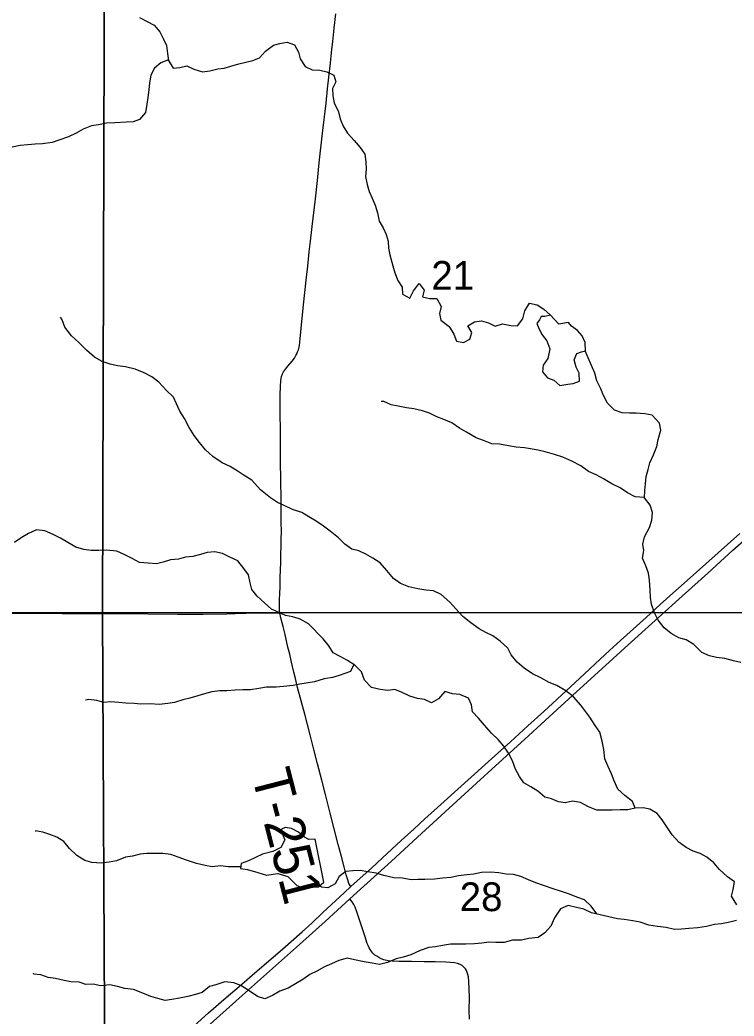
# Model space of a CAD drawing. Extents: x 0 to 34, y 0 to 22.
# Drawn here: x 4.949 to 5.987, y 18.295 to 19.744 of the extents above; entities that cross this region are included whole.
import ezdxf

# ---------------------------------------------------------------- set-up
doc = ezdxf.new("R2010")
doc.units = 0
for name, color, linetype in [('GM_X_Minor_Lake', 7, 'Continuous'), ('GM_X_Minor_River', 7, 'Continuous'), ('GM_X_Section', 7, 'Continuous'), ('GM_X_Section_Text', 7, 'Continuous'), ('GM_X_Township_Road', 7, 'Continuous'), ('GM_X_Township_Road_Text', 7, 'Continuous'), ('GM_X_US_Route', 7, 'Continuous')]:
    doc.layers.add(name, color=color, linetype=linetype)

msp = doc.modelspace()

# ---------------------------------------------------------------- linework, layer by layer
at = {"layer": 'GM_X_Minor_Lake'}
for points in [[(5.7201, 19.3148), (5.7118, 19.3127), (5.7065, 19.3127), (5.7038, 19.3082), (5.7003, 19.3025), (5.7033, 19.2945), (5.7078, 19.2861), (5.7145, 19.2773), (5.719, 19.2659), (5.7162, 19.2519), (5.7093, 19.2421), (5.7085, 19.2323), (5.7156, 19.2238), (5.725, 19.2203), (5.7337, 19.2123), (5.745, 19.2144), (5.753, 19.2155), (5.7621, 19.2188), (5.7618, 19.2306), (5.7574, 19.239), (5.7544, 19.2496), (5.7583, 19.2591), (5.7651, 19.2613), (5.7708, 19.2628), (5.7705, 19.2749), (5.7661, 19.2848), (5.759, 19.2925), (5.7503, 19.299), (5.7462, 19.304), (5.7321, 19.3018)], [(5.7321, 19.3018), (5.7201, 19.3148)], [(5.3778, 18.5526), (5.3687, 18.5523), (5.3623, 18.5558), (5.3536, 18.563), (5.3434, 18.5685), (5.334, 18.5697), (5.3287, 18.5671), (5.3301, 18.561), (5.3338, 18.5519), (5.3277, 18.5405), (5.3163, 18.5349), (5.3011, 18.5309), (5.2809, 18.5213), (5.2703, 18.5176), (5.2695, 18.51), (5.2793, 18.5088), (5.2944, 18.5041), (5.3069, 18.5005), (5.3236, 18.503), (5.3383, 18.4983), (5.3511, 18.4853), (5.3624, 18.481), (5.3745, 18.4828), (5.3825, 18.4835), (5.3905, 18.4902)], [(5.3905, 18.4902), (5.3778, 18.5526)]]:
    msp.add_lwpolyline(points, dxfattribs=at)
at = {"layer": 'GM_X_Minor_River'}
for points in [[(5.1225, 19.7475), (5.1338, 19.7417), (5.1436, 19.7363), (5.1522, 19.7267), (5.1575, 19.7164), (5.1615, 19.7069), (5.163, 19.6955), (5.1648, 19.6852), (5.1715, 19.6738), (5.181, 19.6748), (5.1912, 19.6774), (5.2014, 19.6727), (5.2142, 19.6688), (5.2248, 19.6702), (5.2362, 19.6728), (5.2457, 19.6742), (5.2552, 19.6771), (5.267, 19.6801), (5.2772, 19.6826), (5.2871, 19.6852), (5.2969, 19.6889), (5.3057, 19.6986), (5.3172, 19.7073), (5.3267, 19.7098), (5.3373, 19.7116), (5.3479, 19.7081), (5.3538, 19.6974), (5.356, 19.6875), (5.3631, 19.6765), (5.3737, 19.6718), (5.3846, 19.6709), (5.3948, 19.6689), (5.405, 19.6639), (5.408, 19.654), (5.403, 19.6442), (5.4036, 19.6336), (5.4054, 19.6237), (5.4118, 19.6107), (5.4143, 19.6001), (5.4184, 19.5898), (5.4248, 19.5795), (5.4345, 19.5688), (5.4431, 19.5585), (5.4499, 19.5489), (5.4513, 19.5379), (5.452, 19.5269), (5.4511, 19.5163), (5.4533, 19.5049), (5.4562, 19.4946), (5.4607, 19.4851), (5.4651, 19.4748), (5.4685, 19.4637), (5.471, 19.4516), (5.4766, 19.4417), (5.4811, 19.4321), (5.484, 19.4222), (5.4843, 19.4124), (5.4865, 19.4025), (5.4909, 19.3865), (5.4935, 19.3762), (5.4979, 19.3652), (5.5043, 19.3553), (5.5049, 19.3454), (5.5155, 19.3396), (5.5209, 19.3502), (5.5289, 19.3607), (5.5364, 19.3512), (5.5341, 19.3413), (5.5439, 19.3389), (5.5545, 19.3388), (5.5612, 19.3274), (5.5588, 19.3172), (5.5607, 19.3073), (5.5727, 19.2985), (5.5794, 19.287), (5.5831, 19.2771), (5.5933, 19.2751), (5.6028, 19.2799), (5.6056, 19.2898), (5.5996, 19.2993), (5.6095, 19.3053)], [(5.1646, 19.6863), (5.1537, 19.6819), (5.1442, 19.674), (5.1388, 19.6638), (5.1372, 19.6525), (5.136, 19.6423), (5.1348, 19.6313), (5.1332, 19.6214), (5.1312, 19.6097), (5.1227, 19.5995), (5.1133, 19.5958), (5.1034, 19.5955), (5.0864, 19.5946), (5.0746, 19.5939), (5.0629, 19.5917), (5.0526, 19.5899), (5.0405, 19.5851), (5.0306, 19.5795), (5.0192, 19.574), (5.0051, 19.5692), (4.9956, 19.5658), (4.9816, 19.5641), (4.9706, 19.5634), (4.96, 19.5624), (4.949, 19.5614), (4.9372, 19.5592)], [(5.6095, 19.3053), (5.6197, 19.3067), (5.6299, 19.3036), (5.6397, 19.2986), (5.65, 19.3023), (5.6621, 19.2999), (5.6719, 19.2994), (5.6796, 19.3096), (5.6827, 19.3213), (5.6896, 19.3322), (5.7006, 19.3298), (5.7104, 19.3233), (5.7198, 19.3148)], [(5.8428, 18.5977), (5.8391, 18.6076), (5.8282, 18.6161), (5.818, 18.6253), (5.8124, 18.6375), (5.8087, 18.6478), (5.8032, 18.6592), (5.7987, 18.6695), (5.7973, 18.6832), (5.7951, 18.6953), (5.7918, 18.7083), (5.7851, 18.7182), (5.7769, 18.73), (5.7638, 18.7476), (5.7533, 18.7599), (5.7424, 18.7687), (5.7292, 18.7764), (5.7179, 18.7807), (5.7058, 18.7873), (5.6937, 18.7934), (5.6817, 18.8015), (5.6715, 18.8104), (5.6629, 18.8207), (5.6577, 18.8306), (5.6468, 18.8409), (5.6363, 18.8486), (5.6261, 18.8533), (5.6163, 18.8587), (5.6039, 18.8672), (5.5926, 18.8764), (5.5821, 18.8879), (5.5738, 18.8974), (5.561, 18.9086), (5.5497, 18.914), (5.5388, 18.9148), (5.527, 18.9169), (5.5142, 18.9196), (5.5021, 18.9247), (5.4919, 18.932), (5.4818, 18.9435), (5.4721, 18.9546), (5.4615, 18.9615), (5.4513, 18.9673), (5.4415, 18.9723), (5.431, 18.9743), (5.4208, 18.9816), (5.4118, 18.9912), (5.3998, 19.0008), (5.39, 19.0081), (5.3794, 19.0154), (5.3685, 19.0216), (5.3583, 19.0278), (5.3451, 19.0324), (5.333, 19.0382), (5.3232, 19.0425), (5.3131, 19.0491), (5.2984, 19.061), (5.286, 19.0747), (5.2747, 19.0817), (5.2646, 19.0882), (5.2544, 19.0948), (5.2427, 19.1002), (5.2291, 19.1091), (5.2186, 19.119), (5.2096, 19.1294), (5.2018, 19.1397), (5.1947, 19.1515), (5.188, 19.1645), (5.1809, 19.1752), (5.1764, 19.1858), (5.1719, 19.1954), (5.1614, 19.2057), (5.1505, 19.2172), (5.1404, 19.2253), (5.1295, 19.2311), (5.1162, 19.2365), (5.1023, 19.2397), (5.0905, 19.2413), (5.08, 19.2437), (5.0682, 19.2472), (5.0569, 19.2538), (5.0453, 19.2641), (5.0344, 19.2749), (5.0235, 19.2848), (5.0141, 19.2974), (5.0101, 19.3081), (5.0078, 19.3119)], [(5.9511, 18.8194), (5.9401, 18.8241), (5.9281, 18.8359), (5.9172, 18.8425), (5.9066, 18.8456), (5.8953, 18.8518), (5.8852, 18.8603), (5.8765, 18.8713), (5.8709, 18.882), (5.8669, 18.8946), (5.8655, 18.9041), (5.8648, 18.9147), (5.8638, 18.9295), (5.8623, 18.9394), (5.8583, 18.9504), (5.8538, 18.9615), (5.8554, 18.9725), (5.8544, 18.982), (5.8567, 18.9926), (5.864, 19.0058), (5.8672, 19.0167), (5.8684, 19.0277), (5.8647, 19.0384), (5.8565, 19.0491), (5.8569, 19.0597), (5.8578, 19.0696), (5.859, 19.0802), (5.8621, 19.0904), (5.8645, 19.1002), (5.8699, 19.1119), (5.8745, 19.1237), (5.8765, 19.1339), (5.8804, 19.1475), (5.8782, 19.1578), (5.8677, 19.1696), (5.8571, 19.1712), (5.8446, 19.1725), (5.8348, 19.1722), (5.8242, 19.1727), (5.8129, 19.1766), (5.8027, 19.1866), (5.7968, 19.198), (5.7931, 19.2075), (5.7871, 19.2194), (5.7842, 19.2304), (5.7793, 19.2418), (5.7749, 19.2529), (5.7704, 19.2627)], [(5.8565, 19.0498), (5.8428, 19.0504), (5.8319, 19.0562), (5.8214, 19.0638), (5.8089, 19.0693), (5.7969, 19.077), (5.7863, 19.0824), (5.775, 19.0874), (5.7641, 19.0955), (5.7509, 19.1025), (5.7381, 19.1083), (5.7256, 19.1122), (5.7124, 19.1161), (5.7018, 19.1185), (5.6821, 19.1217), (5.67, 19.123), (5.6591, 19.1246), (5.6458, 19.127), (5.6345, 19.1279), (5.6224, 19.1326), (5.6118, 19.1365), (5.5979, 19.1446), (5.5877, 19.1507), (5.5764, 19.158), (5.5651, 19.1631), (5.5549, 19.167), (5.544, 19.1724), (5.5338, 19.1755), (5.5213, 19.1787), (5.5107, 19.1799), (5.4986, 19.1823), (5.4884, 19.1843), (5.4775, 19.189), (5.4737, 19.1894)], [(5.2208, 18.9695), (5.2113, 18.9666), (5.1999, 18.964), (5.1893, 18.963), (5.1794, 18.9601), (5.1676, 18.959), (5.157, 18.9554), (5.1472, 18.9532), (5.135, 18.9541), (5.1226, 18.9553), (5.112, 18.9607), (5.1003, 18.9665), (5.0897, 18.9716), (5.0746, 18.9732), (5.0636, 18.9726), (5.0523, 18.9727), (5.0417, 18.9739), (5.03, 18.9775), (5.0183, 18.984), (5.0077, 18.9906), (4.9968, 18.996), (4.9851, 19.001), (4.9726, 19.0027), (4.9612, 18.9971), (4.9506, 18.9908), (4.941, 18.984)], [(5.9908, 18.4574), (5.9829, 18.4697), (5.9857, 18.4795), (5.9873, 18.4909), (5.9771, 18.4978), (5.9655, 18.5085), (5.9572, 18.5185), (5.9474, 18.5265), (5.9373, 18.5319), (5.9271, 18.5355), (5.9173, 18.5405), (5.9063, 18.5482), (5.8966, 18.5589), (5.8824, 18.5807), (5.8749, 18.5902), (5.8643, 18.5964), (5.8545, 18.5984), (5.8428, 18.5977), (5.8322, 18.5956), (5.8212, 18.5953), (5.8094, 18.5947), (5.7871, 18.5949), (5.775, 18.5999), (5.7637, 18.6061), (5.752, 18.6081), (5.7414, 18.6056), (5.7315, 18.6072), (5.7213, 18.6114), (5.7115, 18.6138), (5.7017, 18.6226), (5.6912, 18.6288), (5.681, 18.6346), (5.675, 18.6441), (5.6691, 18.6544), (5.6646, 18.6666), (5.659, 18.6777), (5.6519, 18.688), (5.6441, 18.6979), (5.6343, 18.7068), (5.6242, 18.7186), (5.6152, 18.7286), (5.6065, 18.7381), (5.6051, 18.748), (5.6007, 18.7579), (5.5882, 18.763), (5.5776, 18.7642), (5.5663, 18.7677), (5.5571, 18.7568), (5.5468, 18.7512), (5.5366, 18.7559), (5.5264, 18.7571), (5.5155, 18.7607), (5.5045, 18.7661), (5.4936, 18.7704), (5.4834, 18.7689), (5.4724, 18.7706), (5.4599, 18.7733), (5.4494, 18.7841), (5.445, 18.7962), (5.4356, 18.8058), (5.425, 18.8128), (5.4141, 18.8185), (5.4039, 18.8236), (5.3976, 18.8339), (5.3893, 18.8442), (5.3683, 18.8657), (5.3562, 18.8726), (5.3453, 18.8761), (5.3347, 18.8781), (5.3241, 18.8828), (5.3143, 18.8874), (5.3042, 18.8963), (5.2933, 18.9062), (5.2858, 18.9158), (5.2832, 18.9257), (5.2811, 18.9371), (5.2743, 18.9466), (5.2653, 18.9577), (5.254, 18.9631), (5.2431, 18.9682), (5.2321, 18.9706), (5.2208, 18.9695)], [(5.9964, 18.8099), (5.9858, 18.8122), (5.9734, 18.8154), (5.9613, 18.817), (5.9511, 18.8194)], [(5.4342, 18.8067), (5.4294, 18.7964), (5.4127, 18.7909), (5.4032, 18.7879), (5.3907, 18.7858), (5.3767, 18.7817), (5.3649, 18.7796), (5.3554, 18.7781), (5.346, 18.776), (5.3319, 18.775), (5.3213, 18.7739), (5.3073, 18.7737), (5.2959, 18.7719), (5.2838, 18.7701), (5.2728, 18.7698), (5.2615, 18.7696), (5.2493, 18.7686), (5.2395, 18.7683), (5.2277, 18.7669), (5.2171, 18.7643), (5.2072, 18.7614), (5.1958, 18.7577), (5.1856, 18.7555), (5.1735, 18.7515), (5.1636, 18.75), (5.1511, 18.7486), (5.1378, 18.7495), (5.1246, 18.7493), (5.1147, 18.7501), (5.1026, 18.7506), (5.0924, 18.7515), (5.0807, 18.7524), (5.0705, 18.7517), (5.0603, 18.7545), (5.0489, 18.7557), (5.044, 18.755)], [(5.2698, 18.5126), (5.2513, 18.5124), (5.24, 18.5141), (5.2282, 18.5127), (5.218, 18.5147), (5.2055, 18.5174), (5.1908, 18.5221), (5.1787, 18.5264), (5.1678, 18.5303), (5.1564, 18.532), (5.1451, 18.5317), (5.133, 18.5318), (5.1235, 18.5308), (5.1121, 18.5282), (5.1022, 18.5268), (5.0889, 18.5212), (5.0783, 18.5194), (5.0669, 18.5177), (5.0533, 18.5189), (5.0431, 18.5217), (5.0315, 18.529), (5.0209, 18.539), (5.0123, 18.5493), (5.0021, 18.5555), (4.9923, 18.5594), (4.9818, 18.5629), (4.9712, 18.5649), (4.9715, 18.5641)], [(5.7871, 18.4441), (5.7791, 18.4553), (5.7693, 18.4645), (5.758, 18.4684), (5.7478, 18.4727), (5.7357, 18.4766), (5.724, 18.4805), (5.71, 18.4852), (5.6987, 18.4895), (5.6878, 18.4934), (5.6768, 18.4984), (5.6663, 18.5012), (5.6553, 18.5017), (5.6447, 18.5037), (5.6326, 18.5049), (5.6197, 18.5043), (5.6087, 18.5021), (5.5985, 18.5011), (5.5863, 18.4993), (5.5753, 18.4971), (5.5628, 18.4961), (5.5511, 18.4947), (5.5374, 18.4941), (5.5272, 18.4942), (5.5174, 18.4935), (5.5049, 18.4959), (5.492, 18.4964), (5.4777, 18.5), (5.4667, 18.5031), (5.4546, 18.5051), (5.4433, 18.5072), (5.4327, 18.5069), (5.4224, 18.5055), (5.4129, 18.4987), (5.4067, 18.4878), (5.3961, 18.4818), (5.3872, 18.4828), (5.3843, 18.485)], [(5.9902, 18.4343), (5.9807, 18.4321), (5.9686, 18.4296), (5.9583, 18.4285), (5.9466, 18.4256), (5.9341, 18.4238), (5.9208, 18.4228), (5.9106, 18.4218), (5.9003, 18.4215), (5.8879, 18.4243), (5.8754, 18.4256), (5.8629, 18.4276), (5.8501, 18.4319), (5.8395, 18.4339), (5.827, 18.4359), (5.8172, 18.4371), (5.7794, 18.4458), (5.7684, 18.4509), (5.7579, 18.4536), (5.7458, 18.4564), (5.7347, 18.4516), (5.7259, 18.4384), (5.7205, 18.4263), (5.7117, 18.4165), (5.7022, 18.4098), (5.6878, 18.4084), (5.6779, 18.4058), (5.6647, 18.406), (5.6525, 18.4023), (5.6404, 18.4024), (5.6302, 18.4029), (5.6203, 18.4015), (5.6097, 18.4004), (5.5969, 18.4002), (5.5866, 18.4003), (5.5745, 18.4), (5.5628, 18.3982), (5.5529, 18.3961), (5.543, 18.395), (5.5305, 18.391), (5.5168, 18.3847), (5.5058, 18.381), (5.4956, 18.3788), (5.483, 18.3736), (5.4713, 18.3707), (5.4607, 18.3723), (5.4493, 18.3743), (5.435, 18.3771), (5.4244, 18.3795), (5.4122, 18.3762), (5.4016, 18.3717), (5.3913, 18.3669), (5.3803, 18.3609), (5.37, 18.3561), (5.3601, 18.3486), (5.3491, 18.3423), (5.3388, 18.3359), (5.3267, 18.3315), (5.316, 18.3255), (5.3046, 18.3207), (5.294, 18.3238), (5.2805, 18.3331), (5.2699, 18.34), (5.2597, 18.3439), (5.2465, 18.3452), (5.2336, 18.3407), (5.2241, 18.3386), (5.2138, 18.3299), (5.2039, 18.327), (5.1929, 18.3241), (5.1804, 18.3215), (5.1694, 18.3197), (5.1599, 18.3183), (5.149, 18.3211), (5.1391, 18.3238), (5.1271, 18.3289), (5.1139, 18.3343), (5.1014, 18.3356), (5.0904, 18.3383), (5.0795, 18.3407), (5.0662, 18.3393), (5.0552, 18.3417), (5.0446, 18.3414), (5.0348, 18.345), (5.0227, 18.3451), (5.0129, 18.3471), (5.0004, 18.3502), (4.9898, 18.3518), (4.9789, 18.3557), (4.969, 18.3566), (4.9683, 18.3581)]]:
    msp.add_lwpolyline(points, dxfattribs=at)
at = {"layer": 'GM_X_Section'}
for points in [[(6.0796, 19.8902), (6.0998, 18.8817), (5.0689, 18.882), (5.0715, 19.8844)], [(5.0715, 19.8844), (5.0689, 18.882), (4.08, 18.8834), (4.0799, 19.8852)], [(5.0723, 18.2003), (5.0689, 18.882), (4.08, 18.8834), (4.0919, 18.2003)], [(5.9868, 17.8455), (6.1027, 17.8448), (6.0998, 18.8817), (5.0689, 18.882), (5.0723, 18.2003), (5.9868, 18.2003)]]:
    msp.add_lwpolyline(points, close=True, dxfattribs=at)
at = {"layer": 'GM_X_Township_Road'}
for points in [[(5.3266, 18.8816), (5.3261, 18.8858), (5.326, 18.8913), (5.326, 18.8959), (5.3261, 18.8999), (5.3262, 18.9033), (5.3264, 18.9079), (5.3268, 18.9211), (5.327, 18.9273), (5.3271, 18.9304), (5.3272, 18.9334), (5.3279, 18.9552), (5.3281, 18.9681), (5.3283, 18.9785), (5.3285, 18.9906), (5.3288, 18.9986), (5.3285, 19.0152), (5.3286, 19.0331), (5.3284, 19.0514), (5.3281, 19.0702), (5.3276, 19.1069), (5.3276, 19.1264), (5.3275, 19.1491), (5.3272, 19.1705), (5.3271, 19.1984), (5.3274, 19.2117), (5.328, 19.2194), (5.3291, 19.2257), (5.3304, 19.2297), (5.332, 19.2324), (5.3347, 19.2361), (5.3379, 19.2404), (5.3446, 19.2481), (5.3477, 19.2524), (5.3496, 19.256), (5.3513, 19.2588), (5.3524, 19.2617), (5.3534, 19.2644), (5.3549, 19.2705), (5.356, 19.2802), (5.3577, 19.2956), (5.3611, 19.3298), (5.3653, 19.3702), (5.367, 19.386), (5.3692, 19.4068), (5.3711, 19.4226), (5.3737, 19.4439), (5.3781, 19.4842), (5.3811, 19.5108), (5.3838, 19.5363), (5.3885, 19.5794), (5.3936, 19.623), (5.3959, 19.6438), (5.3978, 19.6609), (5.4002, 19.6813), (5.4017, 19.6967), (5.4033, 19.7129), (5.4055, 19.7324), (5.408, 19.7531)], [(4.8734, 18.8813), (4.9511, 18.8812), (5.0101, 18.8808), (5.0381, 18.881), (5.0536, 18.8811), (5.0909, 18.8807), (5.1779, 18.8802), (5.2152, 18.8798), (5.2494, 18.8804), (5.2618, 18.8808), (5.2773, 18.8813), (5.2989, 18.8817), (5.3114, 18.8817), (5.3207, 18.8817), (5.3266, 18.8816)], [(5.4298, 18.4837), (5.427, 18.4885), (5.4251, 18.4936), (5.4229, 18.5009), (5.4199, 18.5126), (5.4161, 18.5275), (5.4115, 18.5452), (5.4049, 18.5699), (5.3998, 18.5906), (5.3929, 18.6178), (5.3876, 18.6388), (5.3812, 18.6624), (5.3748, 18.687), (5.3704, 18.7044), (5.3628, 18.7345), (5.3524, 18.7735), (5.3492, 18.7865), (5.3468, 18.7955), (5.3435, 18.81), (5.3408, 18.8218), (5.3383, 18.8322), (5.3362, 18.8412), (5.334, 18.8502), (5.3314, 18.8621), (5.3286, 18.8729), (5.3266, 18.8816)], [(5.6021, 18.2911), (5.6017, 18.3037), (5.602, 18.323), (5.6011, 18.3459), (5.6007, 18.3527), (5.6, 18.3561), (5.599, 18.3591), (5.5978, 18.3617), (5.5962, 18.3644), (5.5942, 18.3668), (5.5914, 18.3688), (5.5884, 18.3706), (5.5847, 18.3719), (5.5803, 18.373), (5.5679, 18.3739), (5.5524, 18.3742), (5.5362, 18.3744), (5.518, 18.3747), (5.4996, 18.375), (5.49, 18.3755), (5.4839, 18.3759), (5.4775, 18.3771), (5.4738, 18.3787), (5.4702, 18.3806), (5.4673, 18.3824), (5.4648, 18.3843), (5.4617, 18.3871), (5.4589, 18.3908), (5.4564, 18.3945), (5.4548, 18.3979), (5.4535, 18.4012), (5.4499, 18.412), (5.445, 18.4266), (5.4383, 18.4473), (5.4358, 18.4539), (5.4339, 18.4578), (5.4314, 18.4616), (5.4283, 18.4661)]]:
    msp.add_lwpolyline(points, dxfattribs=at)
at = {"layer": 'GM_X_US_Route'}
for points in [[(5.1315, 18.2003), (5.1675, 18.2322), (5.2116, 18.2714), (5.2394, 18.2963), (5.2811, 18.3336), (5.3509, 18.3955), (5.3922, 18.4332), (5.4283, 18.4661), (5.4382, 18.475), (5.4887, 18.521), (5.5324, 18.5608), (5.6126, 18.6343), (5.6402, 18.6593), (5.6768, 18.693), (5.7181, 18.7307), (5.7526, 18.7621), (5.7894, 18.7955), (5.8329, 18.8356), (5.8769, 18.8749), (5.9115, 18.9061), (5.9485, 18.9394), (5.9852, 18.9729), (6.0248, 19.0079)], [(5.2021, 18.2813), (5.2228, 18.3001), (5.2487, 18.3224), (5.2675, 18.3386), (5.2862, 18.355), (5.331, 18.3935), (5.3591, 18.418), (5.3729, 18.4306), (5.3886, 18.4457), (5.4206, 18.4751), (5.4298, 18.4837), (5.4434, 18.496), (5.4595, 18.5107), (5.4755, 18.5254), (5.503, 18.5506), (5.5213, 18.5675), (5.5373, 18.5822), (5.5557, 18.5989), (5.6342, 18.6695), (5.6618, 18.6945), (5.6872, 18.7174), (5.7101, 18.7384), (5.749, 18.7742), (5.7695, 18.7932), (5.7921, 18.8146), (5.8057, 18.8272), (5.8219, 18.8418), (5.8588, 18.875), (5.8795, 18.8939), (5.8978, 18.9106), (5.9141, 18.9251), (5.9952, 18.9975)]]:
    msp.add_lwpolyline(points, dxfattribs=at)

# ---------------------------------------------------------------- texts
at = {"layer": 'GM_X_Section_Text'}
for s, p in [('21', (5.5467, 19.3517)), ('28', (5.5879, 18.4481))]:
    msp.add_text(s, height=0.04186, rotation=0, dxfattribs=at).set_placement(p)
at = {"layer": 'GM_X_Township_Road_Text'}
msp.add_text('T-251', height=0.05682, rotation=284.4403, dxfattribs=at).set_placement((5.2849, 18.647))

doc.saveas('drawing.dxf')
